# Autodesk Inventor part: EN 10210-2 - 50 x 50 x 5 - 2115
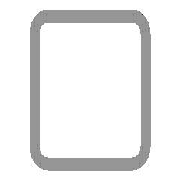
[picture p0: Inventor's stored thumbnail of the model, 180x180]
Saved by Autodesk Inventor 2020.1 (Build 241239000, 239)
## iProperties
IsCustomPart: 1
Created: 2019-01
Part Number: EN 10210-2 - 50 x 50 x 5 - 2115
Material: Stahl, weich
Description: Rohrleitung
Document SubType Name: Modeling
Standard: DIN
Designer: lutzd
Standard Revision: 2006-07
Standards Organization: DIN
Language: de-DE
Size Designation: 50 x 50 x 5
Categories: <MemberInstance><Categories><Category DisplayName="Profile" InternalName="089c4875-fa83-4c05-b084-43b9cc11f5ed" Mnemonic="GRDR"><CategoryParameter DisplayName="
Stock Number: 50 x 50 x 5
Mass: 14497.1 g
Surface Area: 7177.58 cm^2
Volume: 1846.76 cm^3
Density: 7.85 g/cm^3
Appearance: Halbpoliert
G_L: 2115,000 mm
G_W: 50,000 mm
G_H: 50,000 mm
+7405DF6D-380B-4691-AC86-45CA9E1341BC+SCHNITTDETAIL1: Schnittwinkel 90,00 grd
DocNumber: ADSK-014223
Folder: .
Dimensions: 50x50x2115 mm
Mass: 14,497 kg
_CCFamilyMember: 16
_CCFamilyDisplayName: DIN EN 10210-2 (USAS B17.1 quadratisch) - Rohrleitung — In Klammern angegebene Größen wurden aufgehoben
_FrameMemberDoc: Frame Member File
_Version: 15.0.0
_GetPNFromCC: 1
Title: Profil-Bauteil
Author: lutzd
Revision Number: -
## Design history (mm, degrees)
node "Startebene"
node "Endebene"
sketch "Skizze"
  geometry: L1 (-25, -17.5)-(-25, 17.5); L2 (-17.5, 25)-(17.5, 25); L3 (25, 17.5)-(25, -17.5); L4 (17.5, -25)-(-17.5, -25); L5 (-15, 20)-(15, 20); L6 (20, 15)-(20, -15); L7 (15, -20)-(-15, -20); L8 (-20, -15)-(-20, 15); L9 (0, 37.175)-(0, -37.175) reference; L10 (-37.175, 0)-(37.175, 0) reference; A1 r 7.5 centre (-17.5, -17.5) between (-25, -17.5) and (-17.5, -25); A2 r 7.5 centre (-17.5, 17.5) between (-17.5, 25) and (-25, 17.5); A3 r 7.5 centre (17.5, 17.5) between (25, 17.5) and (17.5, 25); A4 r 7.5 centre (17.5, -17.5) between (17.5, -25) and (25, -17.5); A5 r 5 centre (-15, -15) between (-20, -15) and (-15, -20); A6 r 5 centre (-15, 15) between (-15, 20) and (-20, 15); A7 r 5 centre (15, 15) between (20, 15) and (15, 20); A8 r 5 centre (15, -15) between (15, -20) and (20, -15)
  constraints: 16 end point, 16 point on circle, 16 tangent, 8 centre point, 6 equal radius, 4 parallel, 2 perpendicular, 2 other
  dimensions: "d7" = 7.5 radius of A1 (= G_IR); "d10" = 50 distance between parallel lines of L2 L4 (= G_H); "d11" = 50 distance between parallel lines of L1 L3 (= G_W); "d12" = 5 distance between parallel lines of L3 L6 (= G_T); "d15" = 25 distance between parallel lines of L2 L10 (= 0.5 x d10); "d16" = 25 distance between parallel lines of L9 L3 (= 0.5 x d11); "d19" = 5 radius of A5 (= G_T); "d20" = 5 distance between parallel lines of L4 L7 (= G_T)
extrude "Körper" new body sketch "Skizze" stored distance "d3" = 2115 (= G_L); taper "d4" = 0 deg
node "Driven Length"
  sketch "Sketch3"
    geometry: L1 (0, 0)-(10, 0) reference
    constraints: 2 end point, 1 horizontal
  workplane "Work Plane3"
  sketch "Sketch4"
    geometry: L1 (-2, 0)-(12, 0) reference; L2 (-2, 2115)-(12, 2115) reference
    dimensions: "d18" = 2115 distance between parallel lines of L1 L2 (derived)
workplane "Arbeitsebene4"
feature "Trennen1"
body "Solid1"
other parameters: "G_W" = 50 [user parameter; used in 1 equation term], "G_H" = 50 [user parameter; used in 1 equation term], "G_T" = 5 [user parameter; used in 3 equation terms], "G_IR" = 7.5 [user parameter; used in 1 equation term], "G_L" = 2115 (= d18) [user parameter; used in 1 equation term], "G_OFFSET_START" = 0 [user parameter; used in 1 equation term], "G_OFFSET_END" = -575 [user parameter; used in 1 equation term], "d13" = 0 (computed from G_OFFSET_START), "d14" = 2115 (= G_OFFSET_END + B_L), "d17" = 90 deg
